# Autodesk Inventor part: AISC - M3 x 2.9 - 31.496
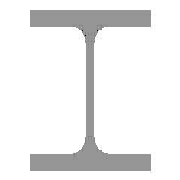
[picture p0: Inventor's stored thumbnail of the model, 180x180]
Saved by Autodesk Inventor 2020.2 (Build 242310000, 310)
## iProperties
Created: 2020-01
Part Number: AISC - M3 x 2.9 - 31.496
Material: Steel, Mild
Description: M-Shape
Document SubType Name: Modeling
Standard: ANSI
Designer: thira
Standards Organization: ANSI
Language: en-US
Size Designation: M3 x 2.9
Categories: <MemberInstance><Categories><Category DisplayName="Structural Shapes" InternalName="089c4875-fa83-4c05-b084-43b9cc11f5ed" Mnemonic="GRDR"><CategoryParameter Dis
Stock Number: M3 x 2.9
Density: 7.85 g/cm^3
Appearance: Semi-Polished
_CCFamilyMember: 14
_CCFamilyDisplayName: ANSI M - M-Shape — Sizes in parentheses have been withdrawn
_FrameMemberDoc: Frame Member File
_Version: 15.0.0
_GetPNFromCC: 1
G_L: 31.496 in
G_W: 2.250 in
G_H: 3.000 in
IsCustomPart: 1
Author: thira
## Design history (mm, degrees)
node "Start plane"
node "End plane"
sketch "Sketch"
  geometry: L1 (-28.575, -38.1)-(-28.575, -34.798); L2 (-28.575, -34.798)-(-10.541, -34.798); L3 (-1.143, -25.4)-(-1.143, 0); L4 (-1.143, 0)-(0, 0); L5 (0, 0)-(0, -38.1); L6 (0, -38.1)-(-28.575, -38.1); L7 (-60, 0)-(80, 0); L8 (0, -60)-(0, 80); L9 (28.575, -38.1)-(28.575, -34.798); L10 (28.575, -34.798)-(10.541, -34.798); L11 (0, -38.1)-(28.575, -38.1); L12 (1.143, -25.4)-(1.143, 0); L13 (1.143, 0)-(0, 0); L14 (-28.575, 38.1)-(-28.575, 34.798); L15 (0, 38.1)-(-28.575, 38.1); L16 (0, 38.1)-(28.575, 38.1); L17 (28.575, 34.798)-(10.541, 34.798); L18 (-28.575, 34.798)-(-10.541, 34.798); L19 (1.143, 25.4)-(1.143, 0); L20 (-1.143, 25.4)-(-1.143, 0); L21 (28.575, 38.1)-(28.575, 34.798); L22 (0, 108.7)-(0, -92.2) reference; L23 (-92.2, 0)-(108.7, 0) reference; A1 r 9.398 centre (-10.541, 25.4) between (-1.143, 25.4) and (-10.541, 34.798); A2 r 9.398 centre (10.541, 25.4) between (10.541, 34.798) and (1.143, 25.4); A3 r 9.398 centre (10.541, -25.4) between (1.143, -25.4) and (10.541, -34.798); A4 r 9.398 centre (-10.541, -25.4) between (-10.541, -34.798) and (-1.143, -25.4); 4 further points
  constraints: 42 end point, 11 symmetric about line, 8 point on circle, 8 point on line, 8 tangent, 4 centre point, 4 collinear, 4 parallel, 3 equal radius, 1 perpendicular, 1 vertical, 13 other
  dimensions: "d1" = 38.1 vertical distance of L1.start L3.end (= 0.5 x G_H); "d2" = 3.302 distance between parallel lines of L2 L6 (= G_T1); "d3" = 28.575 distance from line of L5.end L1 (= 0.5 x G_W); "d4" = 1.143 distance between parallel lines of L5 L3 (= 0.5 x G_T); "d13" = 9.398 radius of A1 (= G_IR)
extrude "Body" new body sketch "Sketch" stored distance "d5" = 800 (= G_L); taper "d6" = 0 deg
node "Driven Length"
  sketch "Sketch4"
    geometry: L1 (0, 0)-(10, 0) reference
    constraints: 2 end point, 1 horizontal
  workplane "Work Plane3"
  sketch "Sketch5"
    geometry: L1 (-2, 0)-(12, 0) reference; L2 (-2, 800)-(12, 800) reference
    dimensions: "d15" = 800 distance between parallel lines of L1 L2 (derived)
body "Solid1"
other parameters: "G_W" = 57.15 [user parameter; used in 1 equation term], "G_H" = 76.2 [user parameter; used in 1 equation term], "G_T" = 2.286 [user parameter; used in 1 equation term], "G_T1" = 3.302 [user parameter; used in 1 equation term], "G_IR" = 9.398 [user parameter; used in 1 equation term], "G_L" = 800 (= d15) [user parameter; used in 1 equation term], "G_OFFSET_START" = 0 [user parameter; used in 1 equation term], "G_OFFSET_END" = 0 [user parameter; used in 1 equation term], "d11" = 0 (computed from G_OFFSET_START), "d12" = 800 (= G_OFFSET_END + B_L), "B_L" = 800 [user parameter; used in 1 equation term], "d14" = 90 deg
